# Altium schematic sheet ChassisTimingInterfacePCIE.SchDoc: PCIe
size B; Engineer: Daniel Sigg; DocumentNumber: 1; Revision: C; SheetNumber: 12; SheetTotal: 12; PageSetup: Record=PageOptions¦CenterHorizontal=True¦CenterVertical=True¦PrintScale=0.72¦XCorrection=1.00¦YCorrection=1.00¦PrintKind=0¦BorderSize=5000000¦LeftOffset=0¦BottomOffset=0¦Orientation=2¦PaperLength=1000¦PaperWidth=1000¦Scale=100¦PaperSource=7¦PrintQuality=-4¦MediaType=1¦DitherType=10¦PaperKind=Tabloid¦PrintScaleMode=1
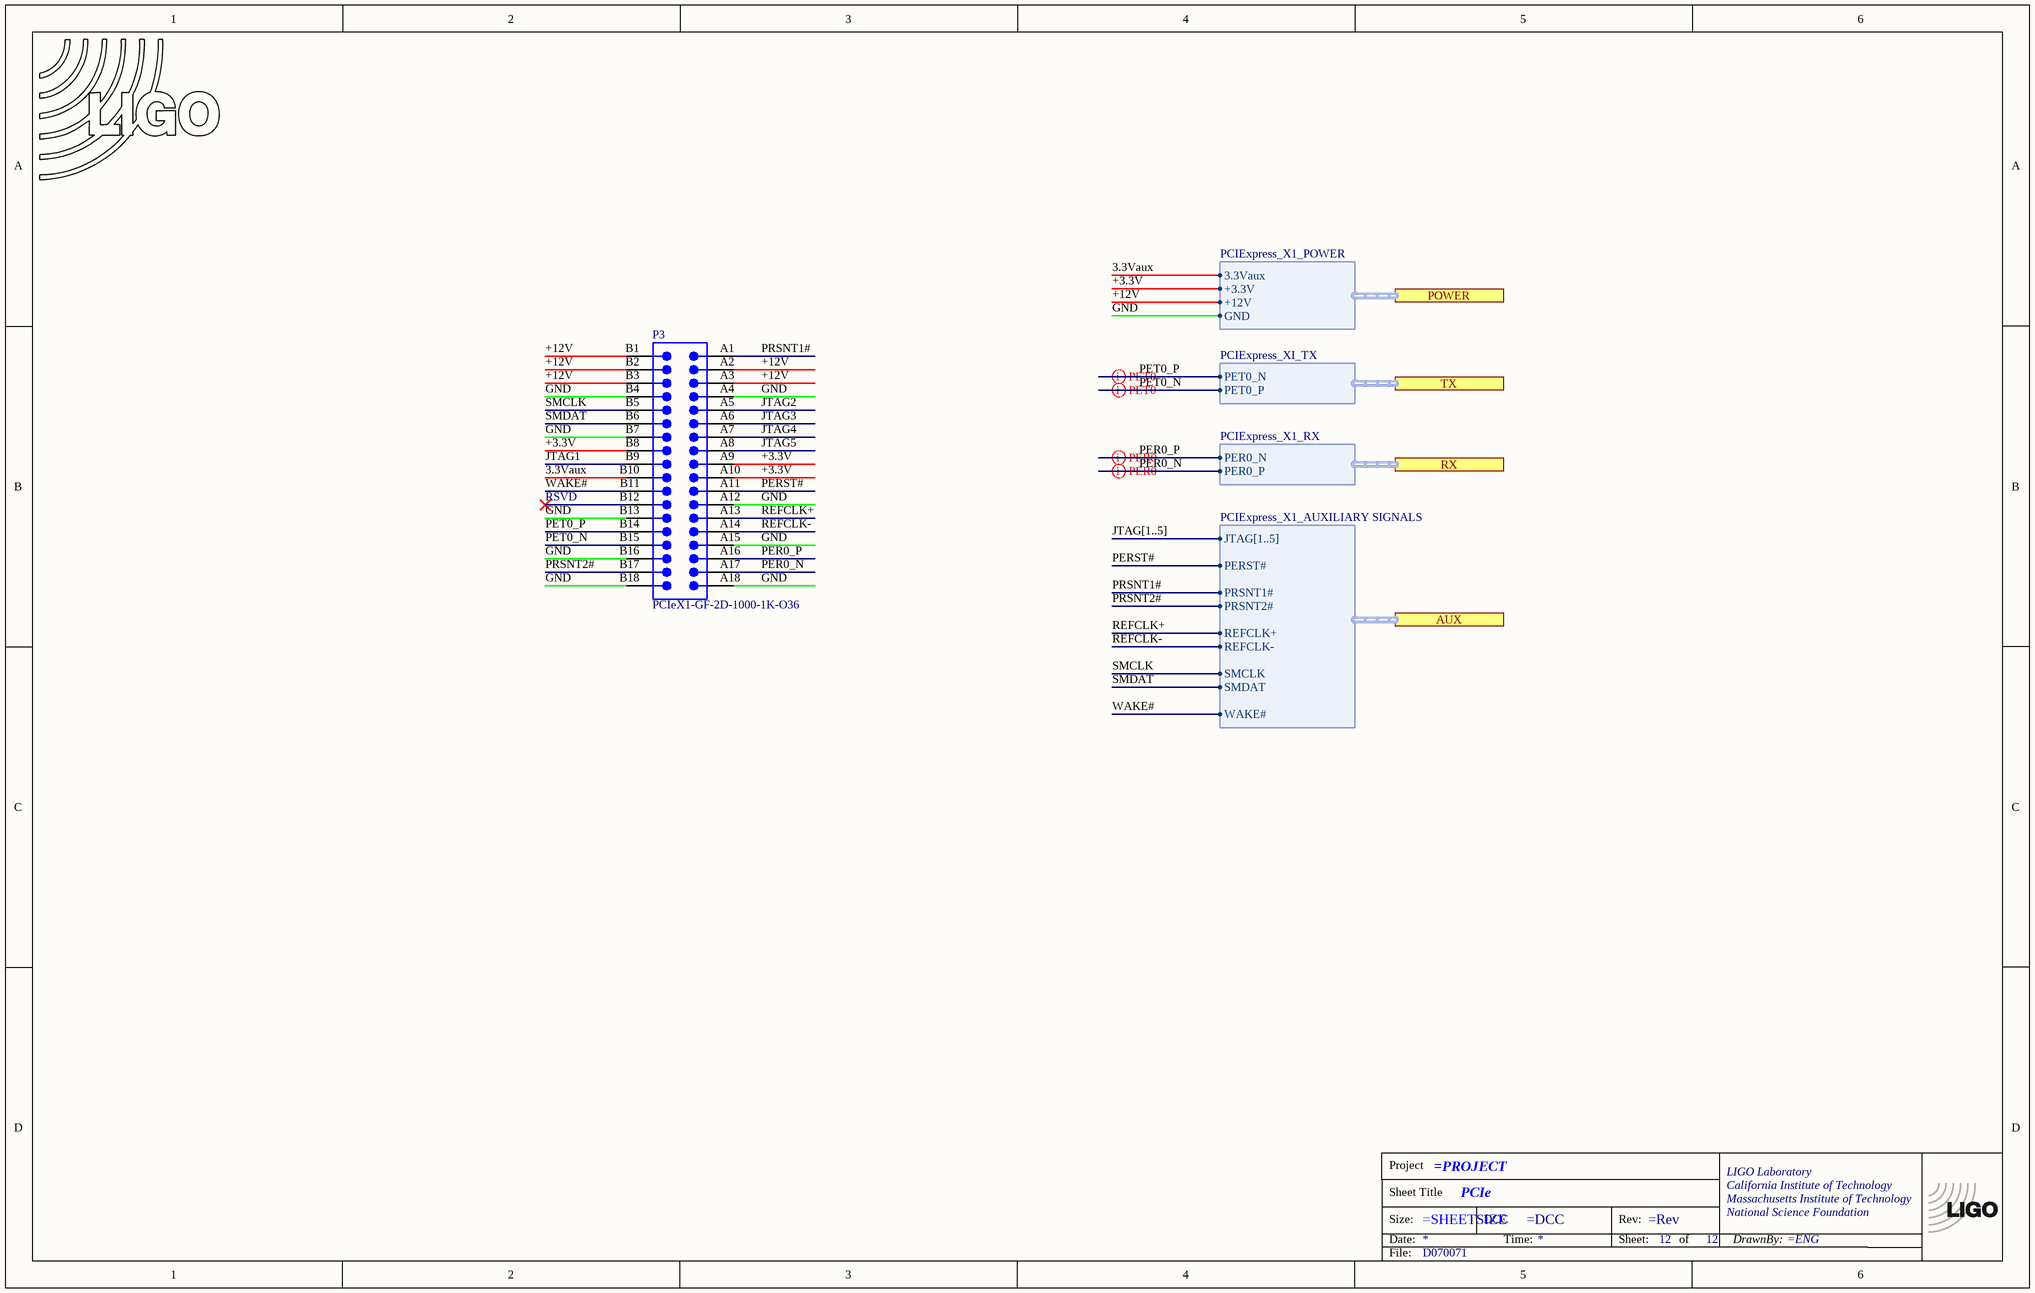
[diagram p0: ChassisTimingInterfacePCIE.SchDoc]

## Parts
*?  TitleBlock  (value not drawn)  (graphical)
LOGO?  LIGO logo  [LIGO_LOGO]  (value not drawn)  (graphical)
P3  PCIeX1-GF-2D-1000-1K-O36  [PCIeX1-GF-2D-1000-1K-O36]  (no BOM)

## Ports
AUX (harness PCIExpress_X1_AUXILIARY SIGNALS), POWER (harness PCIExpress_X1_POWER), RX (harness PCIExpress_X1_RX), TX (harness PCIExpress_XI_TX)

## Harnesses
PCIExpress_X1_POWER: +3.3V, +12V, GND, 3.3Vaux
PCIExpress_XI_TX: PET0_N, PET0_P
PCIExpress_X1_RX: PER0_N, PER0_P
PCIExpress_X1_AUXILIARY SIGNALS: JTAG[1..5], PERST#, PRSNT1#, PRSNT2#, REFCLK+, REFCLK-, SMCLK, SMDAT, WAKE#

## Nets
3.3Vaux: P3.B10 ; port POWER.3.3Vaux
+3.3V: P3.A9 P3.A10 P3.B8 ; port POWER.+3.3V
+12V: P3.A2 P3.A3 P3.B1 P3.B2 P3.B3 ; port POWER.+12V
GND: P3.A4 P3.A12 P3.A15 P3.A18 P3.B4 P3.B7 P3.B13 P3.B16 P3.B18 ; port POWER.GND
JTAG1: P3.B9
JTAG2: P3.A5
JTAG3: P3.A6
JTAG4: P3.A7
JTAG5: P3.A8
PER0_N: P3.A17 ; port RX.PER0_P
PER0_P: P3.A16 ; port RX.PER0_N
PERST#: P3.A11 ; port AUX.PERST#
PET0_N: P3.B15 ; port TX.PET0_P
PET0_P: P3.B14 ; port TX.PET0_N
PRSNT1#: P3.A1 ; port AUX.PRSNT1#
PRSNT2#: P3.B17 ; port AUX.PRSNT2#
REFCLK+: P3.A13 ; port AUX.REFCLK+
REFCLK-: P3.A14 ; port AUX.REFCLK-
SMCLK: P3.B5 ; port AUX.SMCLK
SMDAT: P3.B6 ; port AUX.SMDAT
WAKE#: P3.B11 ; port AUX.WAKE#

Not connected (* = marked no-connect by the designer): P3 B12*

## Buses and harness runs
bus JTAG[1..5]

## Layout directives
differential pair: PER0_N, PER0_P, PET0_N, PET0_P

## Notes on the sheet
- RSVD

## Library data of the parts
LOGO? = LIGO_logo
P3 = CMP-0001-00030-1: Golden finger, PCIeX1, Dual, Opposite, Pitch 1mm, 36-Position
